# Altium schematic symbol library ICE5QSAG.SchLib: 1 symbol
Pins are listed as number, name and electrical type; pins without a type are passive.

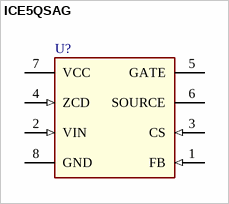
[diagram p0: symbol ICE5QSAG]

## ICE5QSAG
designator U?  (value not drawn)
Quasi-Resonant PWM Controller; Manufacturer: Infineon Technologies
footprint SOIC127P600X175-8N-6
pins: 1 FB (in) "Feedback & Burst Entry/Exit Control", 2 VIN (in) "Input Line OVP & Brownout", 3 CS (in) "Current Sense", 4 ZCD (in) "Zero Crossing Detection", 5 GATE (power) "Gate Driver Output", 6 SOURCE (power) "Source", 7 VCC (power) "Positive Voltage Supply", 8 GND (power) "Ground"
